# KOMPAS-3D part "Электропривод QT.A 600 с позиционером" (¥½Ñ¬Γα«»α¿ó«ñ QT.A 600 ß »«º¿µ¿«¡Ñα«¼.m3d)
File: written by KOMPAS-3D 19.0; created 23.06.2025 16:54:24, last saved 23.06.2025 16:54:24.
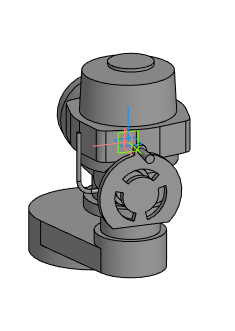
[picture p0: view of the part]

Document properties: Автор: Евгений; Полное имя файла: E:\Dendor Работа Сачек\3D для проектировщиков\3.5 Тип QT.А Электропривод\stp_Электропривод QT.A с позиционером\Электропривод QT.A 600 с позиционером.m3d

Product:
- Part/product: Электропривод QT.A 600 с позиционером

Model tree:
1. Операция без истории:1  (labels: Электропривод QT.A 600 с позиционером)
